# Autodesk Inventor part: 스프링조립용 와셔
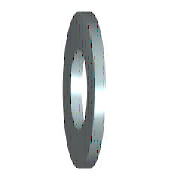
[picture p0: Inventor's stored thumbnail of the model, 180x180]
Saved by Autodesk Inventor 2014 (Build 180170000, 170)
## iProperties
IsCustomPart: 1
Created: 2012-02
Part Number: 스프링조립용 와셔
Material: 강철, 연강
Description: 평면 와셔
Document SubType Name: Modeling
Standard: KS B 1326
Designer: mduedu
Standards Organization: KS
Language: ko-KR
Size Designation: 12x24
Categories: <MemberInstance><Categories><Category DisplayName="조임쇠" InternalName="e4da775c-781d-43d5-af7c-5136215cf5a6" Mnemonic="FSTN"><Category DisplayName="와셔" InternalN
Density: 7.86 g/cm^3
Appearance: 강철
Mass: 5.3954 g
Surface Area: 8.71478 cm^2
Volume: 0.686438 cm^3
Author: mduedu
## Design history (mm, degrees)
sketch "스케치"
  geometry: C1 r 12 at (0, 0); C2 r 7 at (0, 0); 1 further point
  constraints: 2 centre point, 2 coincident
  dimensions: "d0" = 14 diameter of C2 (= SD1); "d1" = 24 diameter of C1 (= SD2)
extrude "본체" new body sketch "스케치" distance "d2" = 2.3 (= SD); taper "d3" = 0 deg
workaxis "Work Axis1"
workplane "Work Plane1"
body "Solid1"
other parameters: "SD1" = 14 [user parameter; used in 1 equation term], "SD2" = 24 [user parameter; used in 1 equation term], "SD" = 2.3 [user parameter; used in 1 equation term], "d4" = 0, "d5" = 0, "d6" = 0, "d7" = 0, "NND" = 12 [user parameter]
